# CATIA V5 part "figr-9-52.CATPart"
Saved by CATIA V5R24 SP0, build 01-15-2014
Part number: Part1
Bounding box of the stored display mesh (mm): x -121 to 121, y -90 to 90, z -40 to 40
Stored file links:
  D:\KAVITA\CATIA V5-6R2014 Project_ Kavita\CATIA V5-6R2014_partfiles\Partfiles\c09_catia_v5-6r2014_prt\figr-9-52.CATPart
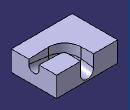
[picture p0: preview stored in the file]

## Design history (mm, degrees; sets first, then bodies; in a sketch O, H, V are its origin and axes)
Body1 (main body)
  Sketch1 on yz-plane, origin (0, 0, 0), H (0, 1, 0), V (0, 0, 1)
    line L1 (-90, 40) -> (90, 40)
    line L2 (90, 40) -> (90, -40)
    line L3 (90, -40) -> (-90, -40)
    line L4 (-90, -40) -> (-90, 40)
    axis line L5 (90, -40) -> (-90, 40)
    horizontal: L1 H, L3 H
    vertical: L2 V, L4 V
    midpoint: O L5
  Pad1: profile Sketch1, direction (1, 0, 0), length 121, mirrored extent
  Loft1: solid, Sections (Sketch4; Sketch3), Spine Sketch2, SectionCouplingPoints ({coupling CouplingPoints (vertex [element of Sketch4 | element of Sketch4]; vertex [element of Sketch3 | element of Sketch3])}; {coupling CouplingPoints (vertex [element of Sketch4 | element of Sketch4]; vertex [element of Sketch3 | element of Sketch3])}; {coupling CouplingPoints (vertex [element of Sketch4 | element of Sketch4]; vertex [element of Sketch3 | element of Sketch3])})
  Sketch2 on face of Pad1, origin (0, 0, 40), H (1, 0, 0), V (0, 1, 0)
    point P1 (121, 0)
    line L1 (121, 0) -> (40.984, 0)
    arc A1 centre (40.984, 40.984) radius 40.984 from (40.984, 0) to (0, 40.984) cw
    line L2 (0, 40.984) -> (0, 90)
    point P5 (0, 90)
    reference projected line E1 (121, 20) -> (121, -20) from edge of Sketch4
    reference projected line E2 (-25.9516, 90) -> (25.9516, 90) from edge of Sketch3
    coincidence: P1 H, P1 E1, P5 E2
    horizontal: L1 H
    tangency: A1 L1, L2 A1
    vertical: L2 V
  Sketch3 on face of Pad1, origin (0, 90, 0), H (-1, 0, 0), V (0, 0, 1)
    line L1 (-25.9516, 40) -> (-25.9516, -8.0968)
    arc A1 centre (0, -8.0968) radius 25.9516 from (-25.9516, -8.0968) to (25.9516, -8.0968) ccw
    point P3 (0, -8.0968)
    line L2 (25.9516, -8.0968) -> (25.9516, 40)
    line L3 (25.9516, 40) -> (-25.9516, 40)
    reference projected line E1 (121, 40) -> (-121, 40) from edge [face of Pad1 | face of Pad1]
    vertical: L1 V, L2 V
    tangency: A1 L1, L2 A1
    horizontal: L3 H
    coincidence: P3 V, L3 E1
  Sketch4 on face of Pad1, origin (121, 0, 0), H (0, 1, 0), V (0, 0, 1)
    line L1 (-20, 40) -> (-20, 21.9917)
    arc A1 centre (0, 21.9917) radius 20 from (-20, 21.9917) to (20, 21.9917) ccw
    point P3 (0, 21.9917)
    line L2 (20, 21.9917) -> (20, 40)
    line L3 (20, 40) -> (-20, 40)
    reference projected line E1 (90, 40) -> (-90, 40) from edge [face of Pad1 | face of Pad1]
    vertical: L1 V, L2 V
    tangency: A1 L1, L2 A1
    horizontal: L3 H
    coincidence: P3 V, L3 E1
